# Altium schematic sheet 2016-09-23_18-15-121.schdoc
size 448 x 287 mm; SheetNumber: 1; SheetTotal: 1
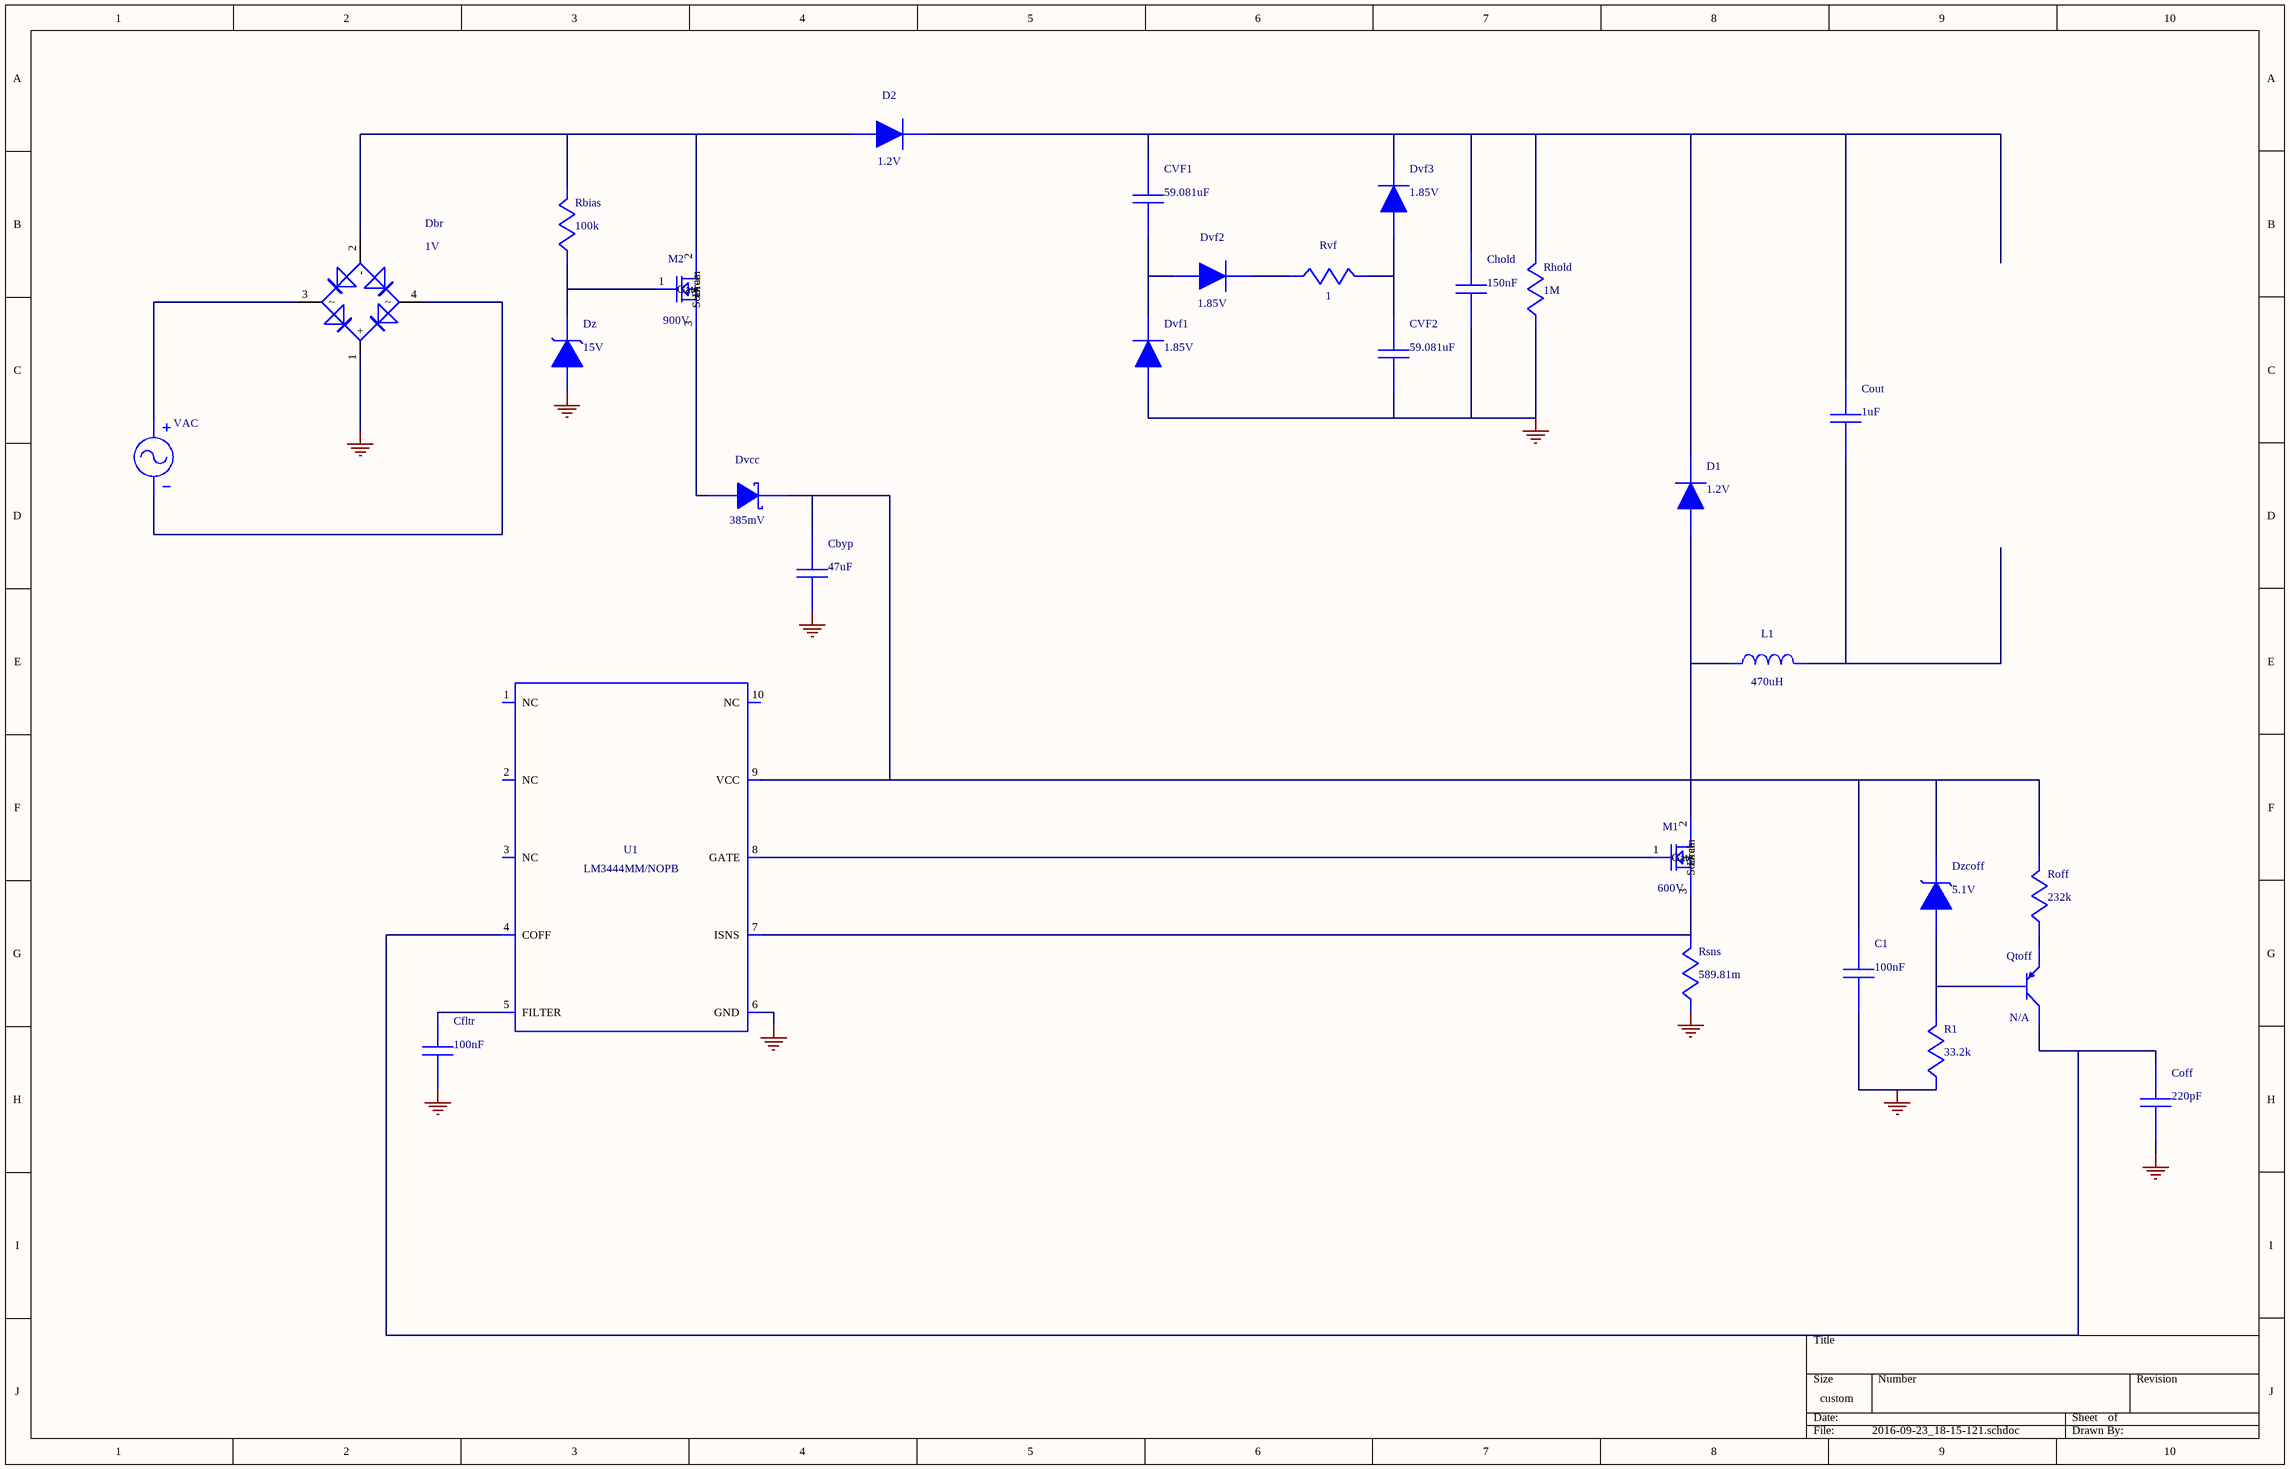
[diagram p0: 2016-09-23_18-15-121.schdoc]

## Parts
C1  value 100nF  (hidden comment: GRM21BR71E104KA01L)
Cbyp  value 47uF  (hidden comment: GRM31CR61A476KE15L)
Cfltr  value 100nF  (hidden comment: GRM21BR71E104KA01L)
Chold  value 150nF  (hidden comment: C3225X7T2J154K)
Coff  value 220pF  (hidden comment: CC0805JRNPO9BN221)
Cout  value 1uF  (hidden comment: GRM31MR71H105KA88L)
CVF1  value 59.081uF  (hidden comment: GENERIC_CAPACITOR)
CVF2  value 59.081uF  (hidden comment: GENERIC_CAPACITOR)
D1  value 1.2V  (hidden comment: CD214B-F3600)
D2  value 1.2V  (hidden comment: CD214B-F3600)
Dbr  value 1V  (hidden comment: HD04-T)
Dvcc  value 385mV  (hidden comment: MBR0520LT1G)
Dvf1  value 1.85V  (hidden comment: GENERIC_DIODE)
Dvf2  value 1.85V  (hidden comment: GENERIC_DIODE)
Dvf3  value 1.85V  (hidden comment: GENERIC_DIODE)
Dz  value 15V  (hidden comment: BZX84C15LT1G)
Dzcoff  value 5.1V  (hidden comment: BZX84C5V1LT1G)
L1  value 470uH  (hidden comment: PM2110-471K-RC)
M1  value 600V  (hidden comment: FCD4N60TM)
M2  value 900V  (hidden comment: STW21N90K5)
Qtoff  MMBT4403  (value not drawn)
R1  value 33.2k  (hidden comment: CRCW040233K2FKED)
Rbias  value 100k  (hidden comment: ERJ-8ENF1003V)
Rhold  value 1M  (hidden comment: CUSTOM3)
Roff  value 232k  (hidden comment: CRCW0402232KFKED)
Rsns  value 589.81m  (hidden comment: CUSTOM4)
Rvf  value 1  (hidden comment: CRCW04021R00FKED)
U1  LM3444MM/NOPB
VAC  WB_PRIM_AC_VOLTAGE_SOURCE  (value not drawn)

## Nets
0: C1.2 Cbyp.2 Cfltr.2 Chold.2 Coff.2 CVF2.2 Dbr.1(+) Dvf1.2(A) Dz.1(A) R1.2 Rhold.1 Rsns.1 U1.6(GND)
NetC1_1: C1.1 Cbyp.1 Dvcc.1(K) Dzcoff.3(K) Roff.1 U1.9(VCC)
NetCfltr_1: Cfltr.1 U1.5(FILTER)
NetChold_1: Chold.1 Cout.1 CVF1.1 D1.1(K) D2.1(K) Dvf3.1(K) Rhold.2
NetCoff_1: Coff.1 Qtoff.3(C) U1.4(COFF)
NetCout_2: Cout.2 L1.2
NetCVF1_2: CVF1.2 Dvf1.1(K) Dvf2.2(A)
NetCVF2_1: CVF2.1 Dvf3.2(A) Rvf.1
NetD1_2: D1.2(A) L1.1 M1.2(Drain)
NetD2_2: D2.2(A) Dbr.2(-) M2.2(Drain) Rbias.1
NetDbr_3: Dbr.3 VAC.1(+)
NetDbr_4: Dbr.4 VAC.2(-)
NetDvcc_2: Dvcc.2(A) M2.3(Source)
NetDvf2_1: Dvf2.1(K) Rvf.2
NetDz_3: Dz.3(K) M2.1(Gate) Rbias.2
NetDzcoff_1: Dzcoff.1(A) Qtoff.1(B) R1.1
NetM1_1: M1.1(Gate) U1.8(GATE)
NetM1_3: M1.3(Source) Rsns.2 U1.7(ISNS)
NetQtoff_2: Qtoff.2(E) Roff.2

Not connected (* = marked no-connect by the designer): U1 1(NC) 2(NC) 3(NC) 10(NC)

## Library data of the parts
C1 Cfltr = GRM21BR71E104KA01L: GRM21BR71E104KA0; Manufacturer Name: MuRata
Cbyp = GRM31CR61A476KE15L: GRM31CR61A476KE1; Manufacturer Name: MuRata
Chold = C3225X7T2J154K: Manufacturer Name: TDK
Coff = CC0805JRNPO9BN221: CC0805JRNPO9BN22; Manufacturer Name: Yageo America
Cout = GRM31MR71H105KA88L: GRM31MR71H105KA8; Manufacturer Name: MuRata
CVF1 = GENERIC_CAPACITOR: CUSTOM1; Manufacturer Name: CUSTOM
CVF2 = GENERIC_CAPACITOR: CUSTOM2; Manufacturer Name: CUSTOM
D1 D2 = CD214B-F3600: Manufacturer Name: Bourns
Dbr = HD04-T: Manufacturer Name: Diodes Inc.
Dvcc = MBR0520LT1G: Manufacturer Name: ON Semiconductor
Dvf1-Dvf3 = GENERIC_DIODE: STTH506B-TR; Manufacturer Name: STMicroelectronics
Dz = BZX84C15LT1G: Manufacturer Name: ON Semiconductor
Dzcoff = BZX84C5V1LT1G: Manufacturer Name: ON Semiconductor
L1 = PM2110-471K-RC: Manufacturer Name: Bourns
M1 = FCD4N60TM: Manufacturer Name: Fairchild Semiconductor
M2 = STW21N90K5: Manufacturer Name: STMicroelectronics
Qtoff = MMBT4403: Manufacturer Name: Fairchild Semiconductor
R1 = CRCW040233K2FKED: Manufacturer Name: Vishay-Dale
Rbias = ERJ-8ENF1003V: Manufacturer Name: Panasonic
Rhold = CUSTOM3: Manufacturer Name: CUSTOM
Roff = CRCW0402232KFKED: Manufacturer Name: Vishay-Dale
Rsns = CUSTOM4: Manufacturer Name: CUSTOM
Rvf = CRCW04021R00FKED: Manufacturer Name: Vishay-Dale
U1 = LM3444MM/NOPB: Manufacturer Name: Texas Instruments
VAC = WB_PRIM_AC_VOLTAGE_SOURCE: WB_PRIM_AC_VOLTA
